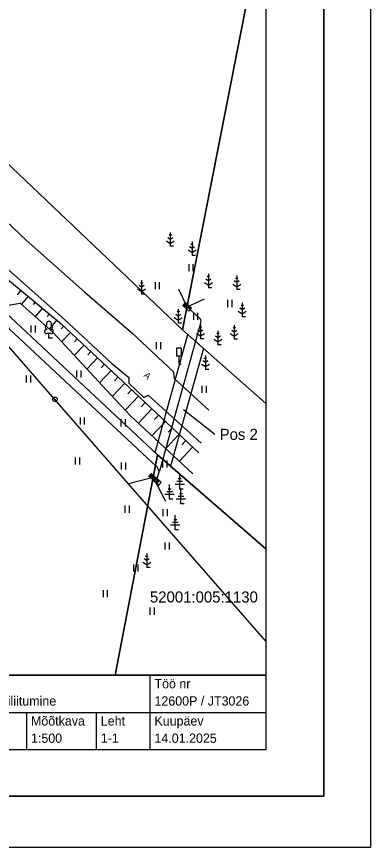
# Model space of a CAD drawing. Extents: x 469301 to 469406, y 6542150 to 6542298.
# Drawn here: x 469367.9 to 469405.9, y 6542149.7 to 6542239 of the extents above; entities that cross this region are included whole.
import ezdxf

# ---------------------------------------------------------------- set-up
doc = ezdxf.new("R2010")
doc.units = 0
for name, color, linetype in [('HALJASTUS', 7, 'Continuous'), ('Hepta_tarbijatoru', 7, 'Continuous'), ('KASUTUSALA', 7, 'Continuous'), ('KPOHULIIN', 7, 'Continuous'), ('LIIKLUS', 7, 'Continuous'), ('MADALPINGE', 7, 'Continuous'), ('PIIR', 7, 'Continuous'), ('POST', 7, 'Continuous'), ('PUU', 7, 'Continuous'), ('RELJEEF', 7, 'Continuous'), ('TEE', 7, 'Continuous'), ('VORMISTUS', 7, 'Continuous')]:
    doc.layers.add(name, color=color, linetype=linetype)

msp = doc.modelspace()

# ---------------------------------------------------------------- linework, layer by layer
at = {"layer": 'HALJASTUS'}
for p, q in [((469386.366, 6542212.352), (469386.366, 6542211.591)), ((469386.821, 6542212.352), (469386.821, 6542211.591)), ((469382.742, 6542210.432), (469382.742, 6542209.671)), ((469383.197, 6542210.432), (469383.197, 6542209.671)), ((469390.544, 6542208.512), (469390.544, 6542207.751)), ((469390.999, 6542208.512), (469390.999, 6542207.751)), ((469386.863, 6542207.147), (469386.863, 6542206.386)), ((469387.318, 6542207.147), (469387.318, 6542206.386)), ((469369.398, 6542205.761), (469369.398, 6542205)), ((469369.853, 6542205.761), (469369.853, 6542205)), ((469382.87, 6542203.99), (469382.87, 6542203.229)), ((469383.325, 6542203.99), (469383.325, 6542203.229)), ((469368.886, 6542200.407), (469368.886, 6542199.646)), ((469369.341, 6542200.407), (469369.341, 6542199.646)), ((469374.301, 6542200.94), (469374.301, 6542200.179)), ((469374.756, 6542200.94), (469374.756, 6542200.179)), ((469387.773, 6542199.298), (469387.773, 6542198.537)), ((469388.228, 6542199.298), (469388.228, 6542198.537)), ((469374.685, 6542195.885), (469374.685, 6542195.124)), ((469375.14, 6542195.885), (469375.14, 6542195.124)), ((469379.076, 6542195.693), (469379.076, 6542194.932)), ((469379.531, 6542195.693), (469379.531, 6542194.932)), ((469374.173, 6542191.577), (469374.173, 6542190.815)), ((469374.628, 6542191.577), (469374.628, 6542190.815)), ((469383.552, 6542191.257), (469383.552, 6542190.495)), ((469384.007, 6542191.257), (469384.007, 6542190.495)), ((469379.118, 6542191.065), (469379.118, 6542190.304)), ((469379.573, 6542191.065), (469379.573, 6542190.304)), ((469379.502, 6542186.415), (469379.502, 6542185.654)), ((469379.957, 6542186.415), (469379.957, 6542185.654)), ((469383.595, 6542186.031), (469383.595, 6542185.27)), ((469384.05, 6542186.031), (469384.05, 6542185.27)), ((469383.808, 6542182.447), (469383.808, 6542181.686)), ((469384.263, 6542182.447), (469384.263, 6542181.686)), ((469380.44, 6542180.101), (469380.44, 6542179.34)), ((469380.895, 6542180.101), (469380.895, 6542179.34)), ((469377.157, 6542177.328), (469377.157, 6542176.567)), ((469377.612, 6542177.328), (469377.612, 6542176.567)), ((469382.188, 6542175.451), (469382.188, 6542174.69)), ((469382.643, 6542175.451), (469382.643, 6542174.69))]:
    msp.add_line(p, q, dxfattribs=at)
at = {"layer": 'Hepta_tarbijatoru'}
for points in [[(469386.196, 6542207.779), (469385.314, 6542209.631)], [(469386.196, 6542207.779), (469388.057, 6542208.638)], [(469382.553, 6542189.429), (469379.901, 6542188.753)], [(469382.553, 6542189.429), (469383.86, 6542186.881)]]:
    msp.add_lwpolyline(points, dxfattribs=at)
at = {"layer": 'KASUTUSALA'}
msp.add_lwpolyline([(469382.753, 6542192.109), (469386.28, 6542204.785), (469387.945, 6542203.307), (469384.421, 6542190.643), (469383.02, 6542191.86)], close=True, dxfattribs=at)
at = {"layer": 'KPOHULIIN'}
msp.add_lwpolyline([(469394.637, 6542171.858), (469371.981, 6542197.833), (469319.828, 6542257.739), (469312.137, 6542266.582)], dxfattribs=at)
at = {"layer": 'LIIKLUS'}
for p, q in [((469385.055, 6542203.325), (469385.055, 6542202.475)), ((469385.555, 6542203.325), (469385.055, 6542203.325)), ((469385.555, 6542203.325), (469385.555, 6542202.475)), ((469385.555, 6542202.475), (469385.055, 6542202.475)), ((469385.305, 6542202.475), (469385.305, 6542201.575)), ((469385.555, 6542201.575), (469385.305, 6542201.575))]:
    msp.add_line(p, q, dxfattribs=at)
at = {"layer": 'MADALPINGE'}
for p, q in [((469386.024, 6542208.25), (469385.716, 6542207.924)), ((469386.351, 6542207.732), (469385.92, 6542208.14)), ((469386.378, 6542207.724), (469385.928, 6542208.149)), ((469386.405, 6542207.716), (469385.937, 6542208.158)), ((469386.433, 6542207.707), (469385.946, 6542208.167)), ((469386.46, 6542207.699), (469385.955, 6542208.176)), ((469386.487, 6542207.691), (469385.963, 6542208.186)), ((469386.514, 6542207.683), (469385.972, 6542208.195)), ((469386.541, 6542207.675), (469385.981, 6542208.204)), ((469386.568, 6542207.666), (469385.989, 6542208.213)), ((469386.595, 6542207.658), (469385.998, 6542208.223)), ((469386.623, 6542207.65), (469386.007, 6542208.232)), ((469386.65, 6542207.642), (469386.016, 6542208.241)), ((469386.677, 6542207.633), (469386.024, 6542208.25)), ((469385.716, 6542207.924), (469386.369, 6542207.307)), ((469385.716, 6542207.924), (469386.677, 6542207.633)), ((469385.727, 6542207.921), (469385.72, 6542207.928)), ((469385.754, 6542207.913), (469385.728, 6542207.937)), ((469385.781, 6542207.904), (469385.737, 6542207.946)), ((469385.808, 6542207.896), (469385.746, 6542207.955)), ((469385.836, 6542207.888), (469385.754, 6542207.965)), ((469385.863, 6542207.88), (469385.763, 6542207.974)), ((469385.89, 6542207.872), (469385.772, 6542207.983)), ((469385.917, 6542207.863), (469385.781, 6542207.992)), ((469385.944, 6542207.855), (469385.789, 6542208.001)), ((469385.971, 6542207.847), (469385.798, 6542208.011)), ((469385.998, 6542207.839), (469385.807, 6542208.02)), ((469386.026, 6542207.83), (469385.815, 6542208.029)), ((469386.053, 6542207.822), (469385.824, 6542208.038)), ((469386.08, 6542207.814), (469385.833, 6542208.047)), ((469386.107, 6542207.806), (469385.841, 6542208.057)), ((469386.134, 6542207.798), (469385.85, 6542208.066)), ((469386.161, 6542207.789), (469385.859, 6542208.075)), ((469386.188, 6542207.781), (469385.868, 6542208.084)), ((469386.216, 6542207.773), (469385.876, 6542208.094)), ((469386.243, 6542207.765), (469385.885, 6542208.103)), ((469386.27, 6542207.757), (469385.894, 6542208.112)), ((469386.297, 6542207.748), (469385.902, 6542208.121)), ((469386.324, 6542207.74), (469385.911, 6542208.13)), ((469386.369, 6542207.307), (469386.677, 6542207.633)), ((469382.317, 6542189.829), (469382.081, 6542189.561)), ((469382.081, 6542189.561), (469382.619, 6542189.087)), ((469382.081, 6542189.561), (469382.855, 6542189.356)), ((469382.089, 6542189.558), (469382.083, 6542189.564)), ((469382.111, 6542189.552), (469382.09, 6542189.571)), ((469382.133, 6542189.547), (469382.097, 6542189.579)), ((469382.155, 6542189.541), (469382.103, 6542189.586)), ((469382.177, 6542189.535), (469382.11, 6542189.594)), ((469382.199, 6542189.529), (469382.117, 6542189.602)), ((469382.221, 6542189.524), (469382.123, 6542189.609)), ((469382.243, 6542189.518), (469382.13, 6542189.617)), ((469382.264, 6542189.512), (469382.137, 6542189.624)), ((469382.286, 6542189.506), (469382.143, 6542189.632)), ((469382.308, 6542189.5), (469382.15, 6542189.64)), ((469382.33, 6542189.495), (469382.157, 6542189.647)), ((469382.352, 6542189.489), (469382.163, 6542189.655)), ((469382.374, 6542189.483), (469382.17, 6542189.662)), ((469382.396, 6542189.477), (469382.177, 6542189.67)), ((469382.418, 6542189.471), (469382.184, 6542189.678)), ((469382.439, 6542189.466), (469382.19, 6542189.685)), ((469382.461, 6542189.46), (469382.197, 6542189.693)), ((469382.483, 6542189.454), (469382.204, 6542189.7)), ((469382.505, 6542189.448), (469382.21, 6542189.708)), ((469382.527, 6542189.443), (469382.217, 6542189.715)), ((469382.549, 6542189.437), (469382.224, 6542189.723)), ((469382.571, 6542189.431), (469382.23, 6542189.731)), ((469382.593, 6542189.425), (469382.237, 6542189.738)), ((469382.615, 6542189.419), (469382.244, 6542189.746)), ((469382.636, 6542189.414), (469382.25, 6542189.753)), ((469382.658, 6542189.408), (469382.257, 6542189.761)), ((469382.68, 6542189.402), (469382.264, 6542189.769)), ((469382.702, 6542189.396), (469382.27, 6542189.776)), ((469382.724, 6542189.39), (469382.277, 6542189.784)), ((469382.746, 6542189.385), (469382.284, 6542189.791)), ((469382.768, 6542189.379), (469382.29, 6542189.799)), ((469382.79, 6542189.373), (469382.297, 6542189.807)), ((469382.811, 6542189.367), (469382.304, 6542189.814)), ((469382.833, 6542189.362), (469382.311, 6542189.822)), ((469382.855, 6542189.356), (469382.317, 6542189.829)), ((469382.855, 6542189.356), (469382.619, 6542189.087)), ((469382.619, 6542189.087), (469382.855, 6542189.356)), ((469382.619, 6542189.087), (469383.157, 6542188.613)), ((469382.826, 6542188.904), (469383.063, 6542189.173)), ((469382.832, 6542188.911), (469382.955, 6542188.803)), ((469382.838, 6542188.917), (469382.961, 6542188.81)), ((469382.844, 6542188.924), (469382.967, 6542188.817)), ((469382.847, 6542188.927), (469382.969, 6542188.82)), ((469382.853, 6542188.934), (469382.975, 6542188.826)), ((469383.393, 6542188.882), (469382.855, 6542189.356)), ((469382.859, 6542188.941), (469382.981, 6542188.833)), ((469382.865, 6542188.948), (469382.987, 6542188.84)), ((469382.871, 6542188.954), (469382.993, 6542188.847)), ((469382.877, 6542188.961), (469382.999, 6542188.853)), ((469382.883, 6542188.968), (469383.005, 6542188.86)), ((469382.889, 6542188.975), (469383.011, 6542188.867)), ((469382.895, 6542188.981), (469383.017, 6542188.874)), ((469382.9, 6542188.988), (469383.023, 6542188.88)), ((469382.905, 6542188.993), (469383.027, 6542188.886)), ((469382.911, 6542189), (469383.033, 6542188.893)), ((469382.917, 6542189.007), (469383.039, 6542188.899)), ((469382.923, 6542189.014), (469383.045, 6542188.906)), ((469382.928, 6542189.019), (469383.05, 6542188.911)), ((469382.934, 6542189.026), (469383.056, 6542188.918)), ((469382.94, 6542189.033), (469383.062, 6542188.925)), ((469382.946, 6542189.039), (469383.068, 6542188.932)), ((469382.949, 6542188.796), (469383.185, 6542189.065)), ((469382.95, 6542189.045), (469383.073, 6542188.937)), ((469382.956, 6542189.051), (469383.079, 6542188.944)), ((469382.962, 6542189.058), (469383.084, 6542188.951)), ((469382.968, 6542189.065), (469383.09, 6542188.957)), ((469382.973, 6542189.07), (469383.095, 6542188.963)), ((469382.979, 6542189.077), (469383.101, 6542188.969)), ((469382.985, 6542189.084), (469383.107, 6542188.976)), ((469382.991, 6542189.091), (469383.113, 6542188.983)), ((469382.995, 6542189.096), (469383.118, 6542188.988)), ((469383.001, 6542189.103), (469383.124, 6542188.995)), ((469383.007, 6542189.109), (469383.13, 6542189.002)), ((469383.013, 6542189.116), (469383.135, 6542189.009)), ((469383.018, 6542189.122), (469383.14, 6542189.014)), ((469383.024, 6542189.128), (469383.146, 6542189.021)), ((469383.03, 6542189.135), (469383.152, 6542189.027)), ((469383.036, 6542189.142), (469383.158, 6542189.034)), ((469383.04, 6542189.147), (469383.163, 6542189.04)), ((469383.046, 6542189.154), (469383.169, 6542189.046)), ((469383.052, 6542189.161), (469383.175, 6542189.053)), ((469383.058, 6542189.167), (469383.181, 6542189.06)), ((469383.157, 6542188.613), (469383.393, 6542188.882))]:
    msp.add_line(p, q, dxfattribs=at)
for points in [[(469319.828, 6542257.739), (469320.471, 6542256.676), (469343.571, 6542230.06), (469351.219, 6542222.88), (469355.016, 6542218.971), (469360.249, 6542214.092), (469364.355, 6542209.323), (469365.778, 6542207.155), (469367.055, 6542205.427), (469381.934, 6542191.507), (469382.877, 6542190.671)], [(469387.528, 6542206.562), (469386.196, 6542207.779)], [(469383.245, 6542190.144), (469387.673, 6542206.059)], [(469383.18, 6542190.157), (469382.891, 6542189.131)]]:
    msp.add_lwpolyline(points, dxfattribs=at)
for centre, radius, start, end in [((469387.191, 6542206.193), 0.5, 344.4513, 47.59463), ((469382.501, 6542190.198), 0.605, 356.49222, 51.47404)]:
    msp.add_arc(centre, radius, start, end, dxfattribs=at)
at = {"layer": 'PIIR'}
for points in [[(469394.637, 6542197.372), (469385.71, 6542205.29), (469351.18, 6542238.06), (469323.75, 6542273.13), (469323.698, 6542273.19)], [(469394.637, 6542266.899), (469323.75, 6542273.13), (469351.18, 6542238.06), (469385.71, 6542205.29), (469394.637, 6542250.957)], [(469312.137, 6542264.766), (469342.49, 6542229.78), (469383.02, 6542191.86), (469394.637, 6542181.77)], [(469394.637, 6542250.957), (469385.71, 6542205.29), (469394.637, 6542197.372)], [(469378.473, 6542168.19), (469383.02, 6542191.86), (469342.49, 6542229.78), (469329.573, 6542168.19)], [(469394.637, 6542181.77), (469383.02, 6542191.86), (469378.473, 6542168.19)]]:
    msp.add_lwpolyline(points, dxfattribs=at)
at = {"layer": 'POST'}
for radius in [0.25, 0.0234]:
    msp.add_circle((469371.981, 6542197.833), radius, dxfattribs=at)
at = {"layer": 'PUU'}
for p, q in [((469384.38, 6542215.427), (469384.255, 6542215.51)), ((469384.38, 6542215.777), (469384.38, 6542214.277)), ((469384.504, 6542215.51), (469384.38, 6542215.427)), ((469383.956, 6542214.866), (469384.38, 6542214.583)), ((469384.38, 6542215.027), (469384.113, 6542215.205)), ((469384.647, 6542215.205), (469384.38, 6542215.027)), ((469384.38, 6542214.583), (469384.804, 6542214.866)), ((469386.726, 6542214.443), (469386.602, 6542214.526)), ((469386.726, 6542214.793), (469386.726, 6542213.293)), ((469386.851, 6542214.526), (469386.726, 6542214.443)), ((469384.74, 6542214.277), (469384.38, 6542214.277)), ((469386.302, 6542213.882), (469386.726, 6542213.599)), ((469386.726, 6542214.043), (469386.46, 6542214.221)), ((469386.993, 6542214.221), (469386.726, 6542214.043)), ((469386.726, 6542213.599), (469387.151, 6542213.882)), ((469387.086, 6542213.293), (469386.726, 6542213.293)), ((469388.476, 6542210.958), (469388.351, 6542211.041)), ((469388.476, 6542211.308), (469388.476, 6542209.808)), ((469388.6, 6542211.041), (469388.476, 6542210.958)), ((469391.527, 6542210.775), (469391.402, 6542210.858)), ((469391.527, 6542211.125), (469391.527, 6542209.625)), ((469391.651, 6542210.858), (469391.527, 6542210.775)), ((469381.297, 6542209.878), (469381.031, 6542210.056)), ((469381.297, 6542210.278), (469381.173, 6542210.361)), ((469381.297, 6542210.628), (469381.297, 6542209.128)), ((469381.422, 6542210.361), (469381.297, 6542210.278)), ((469381.564, 6542210.056), (469381.297, 6542209.878)), ((469388.051, 6542210.398), (469388.476, 6542210.115)), ((469388.476, 6542210.558), (469388.209, 6542210.736)), ((469388.742, 6542210.736), (469388.476, 6542210.558)), ((469388.476, 6542210.115), (469388.9, 6542210.398)), ((469391.103, 6542210.214), (469391.527, 6542209.931)), ((469391.527, 6542210.375), (469391.26, 6542210.552)), ((469391.793, 6542210.552), (469391.527, 6542210.375)), ((469391.527, 6542209.931), (469391.951, 6542210.214)), ((469380.873, 6542209.718), (469381.297, 6542209.435)), ((469381.297, 6542209.435), (469381.722, 6542209.718)), ((469381.657, 6542209.128), (469381.297, 6542209.128)), ((469388.836, 6542209.808), (469388.476, 6542209.808)), ((469391.887, 6542209.625), (469391.527, 6542209.625)), ((469392.111, 6542208.203), (469392.111, 6542206.703)), ((469385.232, 6542207.184), (469385.107, 6542207.267)), ((469385.232, 6542207.534), (469385.232, 6542206.034)), ((469385.356, 6542207.267), (469385.232, 6542207.184)), ((469391.687, 6542207.293), (469392.111, 6542207.01)), ((469392.111, 6542207.453), (469391.845, 6542207.631)), ((469392.111, 6542207.853), (469391.987, 6542207.936)), ((469392.236, 6542207.936), (469392.111, 6542207.853)), ((469392.378, 6542207.631), (469392.111, 6542207.453)), ((469392.111, 6542207.01), (469392.535, 6542207.293)), ((469384.807, 6542206.623), (469385.232, 6542206.34)), ((469385.232, 6542206.784), (469384.965, 6542206.962)), ((469385.498, 6542206.962), (469385.232, 6542206.784)), ((469385.232, 6542206.34), (469385.656, 6542206.623)), ((469392.471, 6542206.703), (469392.111, 6542206.703)), ((469385.592, 6542206.034), (469385.232, 6542206.034)), ((469387.62, 6542205.484), (469387.496, 6542205.567)), ((469387.62, 6542205.834), (469387.62, 6542204.334)), ((469387.745, 6542205.567), (469387.62, 6542205.484)), ((469391.249, 6542205.458), (469391.124, 6542205.541)), ((469391.249, 6542205.808), (469391.249, 6542204.308)), ((469391.373, 6542205.541), (469391.249, 6542205.458)), ((469371.576, 6542204.895), (469371.096, 6542204.895)), ((469371.336, 6542204.42), (469371.336, 6542204.895)), ((469387.196, 6542204.923), (469387.62, 6542204.641)), ((469387.62, 6542205.084), (469387.354, 6542205.262)), ((469387.887, 6542205.262), (469387.62, 6542205.084)), ((469387.62, 6542204.641), (469388.045, 6542204.923)), ((469389.497, 6542204.451), (469389.23, 6542204.628)), ((469389.497, 6542204.851), (469389.372, 6542204.934)), ((469389.497, 6542205.201), (469389.497, 6542203.701)), ((469389.621, 6542204.934), (469389.497, 6542204.851)), ((469389.763, 6542204.628), (469389.497, 6542204.451)), ((469390.824, 6542204.898), (469391.249, 6542204.615)), ((469391.249, 6542205.058), (469390.982, 6542205.236)), ((469391.515, 6542205.236), (469391.249, 6542205.058)), ((469391.249, 6542204.615), (469391.673, 6542204.898)), ((469371.716, 6542204.42), (469371.336, 6542204.42)), ((469387.98, 6542204.334), (469387.62, 6542204.334)), ((469389.072, 6542204.29), (469389.497, 6542204.007)), ((469389.497, 6542204.007), (469389.921, 6542204.29)), ((469389.857, 6542203.701), (469389.497, 6542203.701)), ((469391.609, 6542204.308), (469391.249, 6542204.308)), ((469388.153, 6542201.792), (469387.886, 6542201.969)), ((469388.153, 6542202.192), (469388.029, 6542202.275)), ((469388.153, 6542202.542), (469388.153, 6542201.042)), ((469388.278, 6542202.275), (469388.153, 6542202.192)), ((469388.42, 6542201.969), (469388.153, 6542201.792)), ((469387.729, 6542201.631), (469388.153, 6542201.348)), ((469388.153, 6542201.348), (469388.577, 6542201.631)), ((469388.513, 6542201.042), (469388.153, 6542201.042)), ((469385.395, 6542188.194), (469385.395, 6542189.769)), ((469384.308, 6542187.096), (469384.308, 6542188.671)), ((469385.895, 6542188.694), (469384.895, 6542188.694)), ((469385.695, 6542188.994), (469385.095, 6542188.994)), ((469385.545, 6542189.294), (469385.245, 6542189.294)), ((469384.608, 6542187.896), (469384.008, 6542187.896)), ((469384.458, 6542188.196), (469384.158, 6542188.196)), ((469385.675, 6542187.691), (469385.375, 6542187.691)), ((469385.755, 6542188.194), (469385.395, 6542188.194)), ((469385.525, 6542186.591), (469385.525, 6542188.166)), ((469384.808, 6542187.596), (469383.808, 6542187.596)), ((469384.668, 6542187.096), (469384.308, 6542187.096)), ((469386.025, 6542187.091), (469385.025, 6542187.091)), ((469385.825, 6542187.391), (469385.225, 6542187.391)), ((469385.885, 6542186.591), (469385.525, 6542186.591)), ((469384.92, 6542183.801), (469384.92, 6542185.376)), ((469385.42, 6542184.301), (469384.42, 6542184.301)), ((469385.22, 6542184.601), (469384.62, 6542184.601)), ((469385.07, 6542184.901), (469384.77, 6542184.901)), ((469385.28, 6542183.801), (469384.92, 6542183.801)), ((469381.851, 6542180.507), (469381.584, 6542180.684)), ((469381.851, 6542180.907), (469381.727, 6542180.99)), ((469381.851, 6542181.257), (469381.851, 6542179.757)), ((469381.975, 6542180.99), (469381.851, 6542180.907)), ((469382.118, 6542180.684), (469381.851, 6542180.507)), ((469381.427, 6542180.346), (469381.851, 6542180.063)), ((469381.851, 6542180.063), (469382.275, 6542180.346)), ((469382.211, 6542179.757), (469381.851, 6542179.757))]:
    msp.add_line(p, q, dxfattribs=at)
for centre, radius, start, end in [((469371.166, 6542205.592), 0.233, 109.02174, 253.14154), ((469371.336, 6542205.94), 0.277, 332.5799, 207.4201), ((469371.506, 6542205.592), 0.233, 286.85082, 70.98591), ((469371.098, 6542205.132), 0.238, 90.0016, 269.3953), ((469371.573, 6542205.132), 0.238, 270.6047, 89.9984)]:
    msp.add_arc(centre, radius, start, end, dxfattribs=at)
at = {"layer": 'RELJEEF'}
for p, q in [((469368.326, 6542209.563), (469367.923, 6542209.079)), ((469369.095, 6542208.923), (469368.375, 6542208.059)), ((469369.863, 6542208.283), (469369.641, 6542208.016)), ((469370.632, 6542207.644), (469369.867, 6542206.725)), ((469371.4, 6542207.004), (469371.164, 6542206.72)), ((469372.169, 6542206.364), (469371.358, 6542205.39)), ((469372.923, 6542205.708), (469372.654, 6542205.42)), ((469373.653, 6542205.025), (469372.706, 6542204.013)), ((469374.384, 6542204.342), (469374.085, 6542204.022)), ((469375.114, 6542203.659), (469374.067, 6542202.54)), ((469375.844, 6542202.975), (469375.515, 6542202.624)), ((469376.574, 6542202.292), (469375.428, 6542201.067)), ((469377.305, 6542201.609), (469376.946, 6542201.225)), ((469378.035, 6542200.926), (469376.789, 6542199.594)), ((469378.765, 6542200.243), (469378.376, 6542199.827)), ((469379.494, 6542199.559), (469378.145, 6542198.13)), ((469380.221, 6542198.872), (469379.805, 6542198.43)), ((469380.949, 6542198.185), (469379.519, 6542196.671)), ((469381.676, 6542197.499), (469381.236, 6542197.033)), ((469382.406, 6542196.816), (469380.949, 6542195.259)), ((469383.136, 6542196.132), (469382.7, 6542195.666)), ((469383.866, 6542195.449), (469382.413, 6542193.895)), ((469384.597, 6542194.766), (469384.161, 6542194.3)), ((469385.327, 6542194.083), (469383.876, 6542192.532)), ((469386.057, 6542193.4), (469385.622, 6542192.935)), ((469386.788, 6542192.717), (469385.339, 6542191.169))]:
    msp.add_line(p, q, dxfattribs=at)
for points in [[(469323.33, 6542256.413), (469326.827, 6542252.549), (469333.753, 6542244.795), (469341.089, 6542236.802), (469348.799, 6542228.549), (469356.718, 6542220.922), (469360.278, 6542217.483), (469366.257, 6542211.286), (469372.659, 6542205.955), (469379.321, 6542199.722), (469381.683, 6542197.492), (469387.454, 6542192.094)], [(469323.33, 6542256.413), (469326.354, 6542251.969), (469332.881, 6542244.141), (469340.341, 6542235.897), (469348.123, 6542227.741), (469355.835, 6542219.919), (469359.643, 6542216.74), (469365.449, 6542210.123), (469365.99, 6542208.972), (469366.955, 6542207.944), (469368.26, 6542208.163), (469371.794, 6542205), (469377.984, 6542198.301), (469380.124, 6542196.027), (469386.793, 6542189.814)]]:
    msp.add_lwpolyline(points, dxfattribs=at)
at = {"layer": 'TEE'}
for points in [[(469321.471, 6542265.872), (469323.834, 6542263.278), (469330.319, 6542255.614), (469337.046, 6542247.73), (469344.068, 6542239.945), (469351.964, 6542231.334), (469359.24, 6542224.006), (469363.104, 6542220.414), (469368.893, 6542214.948), (469375.209, 6542209.343), (469380.212, 6542205.014), (469384.737, 6542200.792), (469384.795, 6542200.073), (469388.511, 6542196.655)], [(469319.317, 6542263.482), (469321.496, 6542260.919), (469327.795, 6542253.47), (469334.177, 6542245.146), (469341.399, 6542237.132), (469349.235, 6542228.838), (469356.948, 6542221.192), (469360.43, 6542217.78), (469366.662, 6542212.035), (469373.024, 6542206.414), (469378.054, 6542201.72), (469379.935, 6542200.169), (469379.92, 6542199.582), (469381.553, 6542198.02), (469381.998, 6542198.266), (469387.691, 6542193.138)]]:
    msp.add_lwpolyline(points, dxfattribs=at)
at = {"layer": 'VORMISTUS'}
for p, q in [((469385.786, 6542196.751), (469389.185, 6542194.078)), ((469382.182, 6542168.19), (469382.182, 6542164.19)), ((469335.637, 6542164.19), (469394.637, 6542164.19)), ((469368.909, 6542164.19), (469368.909, 6542160.19)), ((469376.414, 6542164.19), (469376.414, 6542160.19)), ((469382.182, 6542164.19), (469382.182, 6542160.19))]:
    msp.add_line(p, q, dxfattribs=at)
for points in [[(469300.887, 6542298.19), (469405.887, 6542298.19), (469405.887, 6542149.69), (469300.887, 6542149.69)], [(469305.887, 6542155.19), (469400.887, 6542155.19), (469400.887, 6542292.69), (469305.887, 6542292.69)], [(469305.887, 6542292.69), (469400.887, 6542292.69), (469400.887, 6542155.19), (469305.887, 6542155.19)], [(469394.637, 6542168.19), (469312.137, 6542168.19), (469312.137, 6542273.19), (469394.637, 6542273.19)], [(469335.637, 6542168.19), (469394.637, 6542168.19), (469394.637, 6542160.19), (469335.637, 6542160.19)]]:
    msp.add_lwpolyline(points, close=True, dxfattribs=at)

# ---------------------------------------------------------------- texts
at = {"layer": 'PIIR'}
msp.add_text('52001:005:1130', height=1.2, dxfattribs=at).set_placement((469382.192, 6542175.998))
at = {"layer": 'TEE'}
msp.add_text('A', height=0.7, rotation=318.14154, dxfattribs=at).set_placement((469381.471, 6542200.332))
at = {"layer": 'VORMISTUS'}
for s, height, p in [('Pos 2', 1.2, (469389.685, 6542193.478)), ('Töö nr', 1, (469382.68, 6542166.782)), ('52001:005:1130 ja 52001:004:0772 kinnistute elektriliitumine', 1, (469336.135, 6542164.925)), ('12600P / JT3026', 1, (469382.68, 6542164.925)), ('Mõõtkava', 1, (469369.407, 6542162.782)), ('Leht', 1, (469376.912, 6542162.782)), ('Kuupäev', 1, (469382.68, 6542162.782)), ('1:500', 1, (469369.407, 6542160.925)), ('1-1', 1, (469376.912, 6542160.925)), ('14.01.2025', 1, (469382.68, 6542160.925))]:
    msp.add_text(s, height=height, dxfattribs=at).set_placement(p)

doc.saveas('drawing.dxf')
